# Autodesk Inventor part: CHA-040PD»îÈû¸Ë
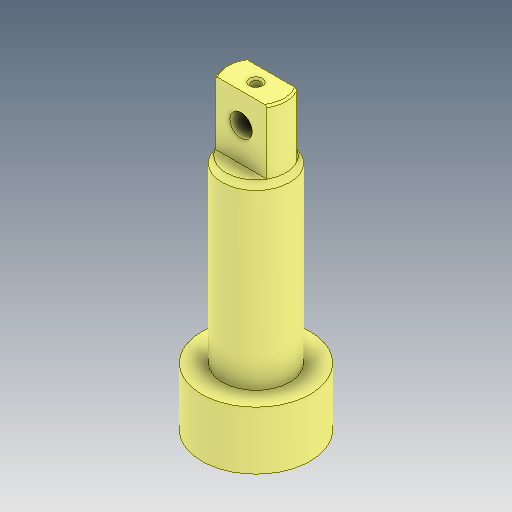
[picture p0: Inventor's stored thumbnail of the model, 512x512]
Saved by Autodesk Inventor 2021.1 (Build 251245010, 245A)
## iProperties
Created: 2021-05
Part Number: CHA-040PD»îÈû¸Ë
Material: Ogólny
Document SubType Name: Modeling
Designer: user
Density: 1 g/cm^3
Appearance: Domyślna
Author: user
Revision Number: ÈÎºÎ
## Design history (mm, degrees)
feature "ÇÐ³ý-À­Éì18"
node "Bryła1"
